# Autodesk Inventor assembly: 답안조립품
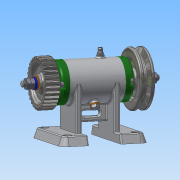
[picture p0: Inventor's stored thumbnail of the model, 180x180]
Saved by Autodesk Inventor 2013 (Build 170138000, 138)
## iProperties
Created: 2016-07
Part Number: 답안조립품
Document SubType Name: Assembly
Designer: Administrator
Author: Administrator
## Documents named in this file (16)
- C:\Users\Administrator\Desktop\460708V1014\답안조립품.iam
- C:\Users\Administrator\Desktop\460708V1014\본체.ipt
- C:\Users\Administrator\Desktop\460708V1014\V벨트풀리.ipt
- C:\Users\Administrator\Desktop\460708V1014\너트 M 8.ipt
- C:\Users\Administrator\Desktop\460708V1014\니플 M 6 x 0.75.ipt
- C:\Users\Administrator\Desktop\460708V1014\베어링 15 x 32 x 9.ipt
- C:\Users\Administrator\Desktop\460708V1014\볼트 M 6 x 8.ipt
- C:\Users\Administrator\Desktop\460708V1014\볼트 M4 x 12.ipt
- C:\Users\Administrator\Desktop\460708V1014\스퍼기어.ipt
- C:\Users\Administrator\Desktop\460708V1014\스프링와셔 8.ipt
- C:\Users\Administrator\Desktop\460708V1014\오일 실 15 25 7.ipt
- C:\Users\Administrator\Desktop\460708V1014\와셔 6x11.5.ipt
- C:\Users\Administrator\Desktop\460708V1014\와셔 8x17.ipt
- C:\Users\Administrator\Desktop\460708V1014\축.ipt
- C:\Users\Administrator\Desktop\460708V1014\키 3 x 3 x 12.ipt
- C:\Users\Administrator\Desktop\460708V1014\커버.ipt
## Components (11 placed, 3 different names)
1. V벨트풀리:1
2. KS B 2023 6002 - 15 x 32 x 9:1
3. KS B 2023 6002 - 15 x 32 x 9:2
4. ISO 4762 M4 x 12:1
5. ISO 4762 M4 x 12:3
6. ISO 4762 M4 x 12:4
7. ISO 4762 M4 x 12:5
8. ISO 4762 M4 x 12:2
9. ISO 4762 M4 x 12:6
10. ISO 4762 M4 x 12:7
11. ISO 4762 M4 x 12:8
